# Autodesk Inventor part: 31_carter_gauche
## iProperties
Created: 2002-11
Part Number: 31_carter_gauche
Material: Par défaut
Document SubType Name: Modélisation
Designer: poste-2
Control State: 0
Master: False
Checked Out: False
Shininess: 60.0
Length Units: 11269
Angle Units: 11279
Time Units: 11290
Mass Units: 11283
Length Display Precision: 3
Angle Display Precision: 2
Compacted: True
Density: 0.0
Volumn: 0.0
Area: 0.0
PropertySet Name: Model Information
Author: poste-2
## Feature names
1. Extrusion1
2. Balayage1
3. Symétrie1 [Mirror]
4. Extrusion2
5. Extrusion3
6. Extrusion4
7. Congé1 [Fillet]
8. Extrusion8
9. Extrusion9
10. Extrusion10
11. Extrusion11
12. Chanfrein1 [Chamfer]
13. Extrusion12
14. Extrusion13
15. Extrusion14
16. Extrusion15
17. Extrusion16
18. Extrusion17
19. Extrusion18
20. Extrusion19
21. Extrusion21
22. Extrusion22
23. Extrusion23
24. Réseau rectangulaire1 [Rectangular Pattern]
25. Extrusion24
26. Extrusion25
27. Extrusion26
28. Réseau rectangulaire2 [Rectangular Pattern]
29. Extrusion27
30. Extrusion28
31. Réseau rectangulaire3 [Rectangular Pattern]
32. Extrusion29
33. Extrusion30
34. Révolution1 [Revolution]
35. Réseau rectangulaire4 [Rectangular Pattern]
36. Extrusion31
37. Extrusion32
38. Extrusion33
39. Extrusion35
40. Extrusion36
41. Extrusion37
42. Extrusion38
43. Extrusion39
44. Extrusion40
45. Extrusion41
46. Extrusion44
47. Extrusion45
48. Réseau rectangulaire5 [Rectangular Pattern]
49. Extrusion46
50. Extrusion6
51. Extrusion7
52. Congé2 [Fillet]
53. Extrusion47
54. Perçage1 [Hole]
55. Extrusion48
